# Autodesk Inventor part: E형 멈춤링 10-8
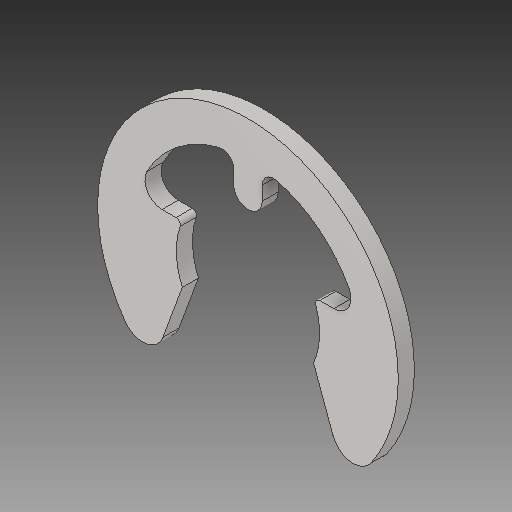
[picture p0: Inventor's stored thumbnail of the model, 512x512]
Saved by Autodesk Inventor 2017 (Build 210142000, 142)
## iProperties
Created: 2024-08
Part Number: E형 멈춤링 10-8
Material: 일반
Description: 일반용 테이퍼 및 줄어든 횡단면 리테이닝 링 - E-링 외부 시리즈 3CM1 리테이닝 링
Document SubType Name: Modeling
Designer: MRC
Density: 1 g/cm^3
Appearance: 기본값
Author: jhkim
Sending System: Autodesk Inventor 2025
Preprocessor: ST-DEVELOPER v20
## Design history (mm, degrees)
feature "Solid1"
node "솔리드1"
